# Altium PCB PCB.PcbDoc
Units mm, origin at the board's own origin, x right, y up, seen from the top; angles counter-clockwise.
Board outline 65 x 50 mm, 2 copper layers (Top Layer, Bottom Layer); 104 components, 73 nets, 355 pads, 371 vias.
Unrouted connection lines stored in the file: 2.
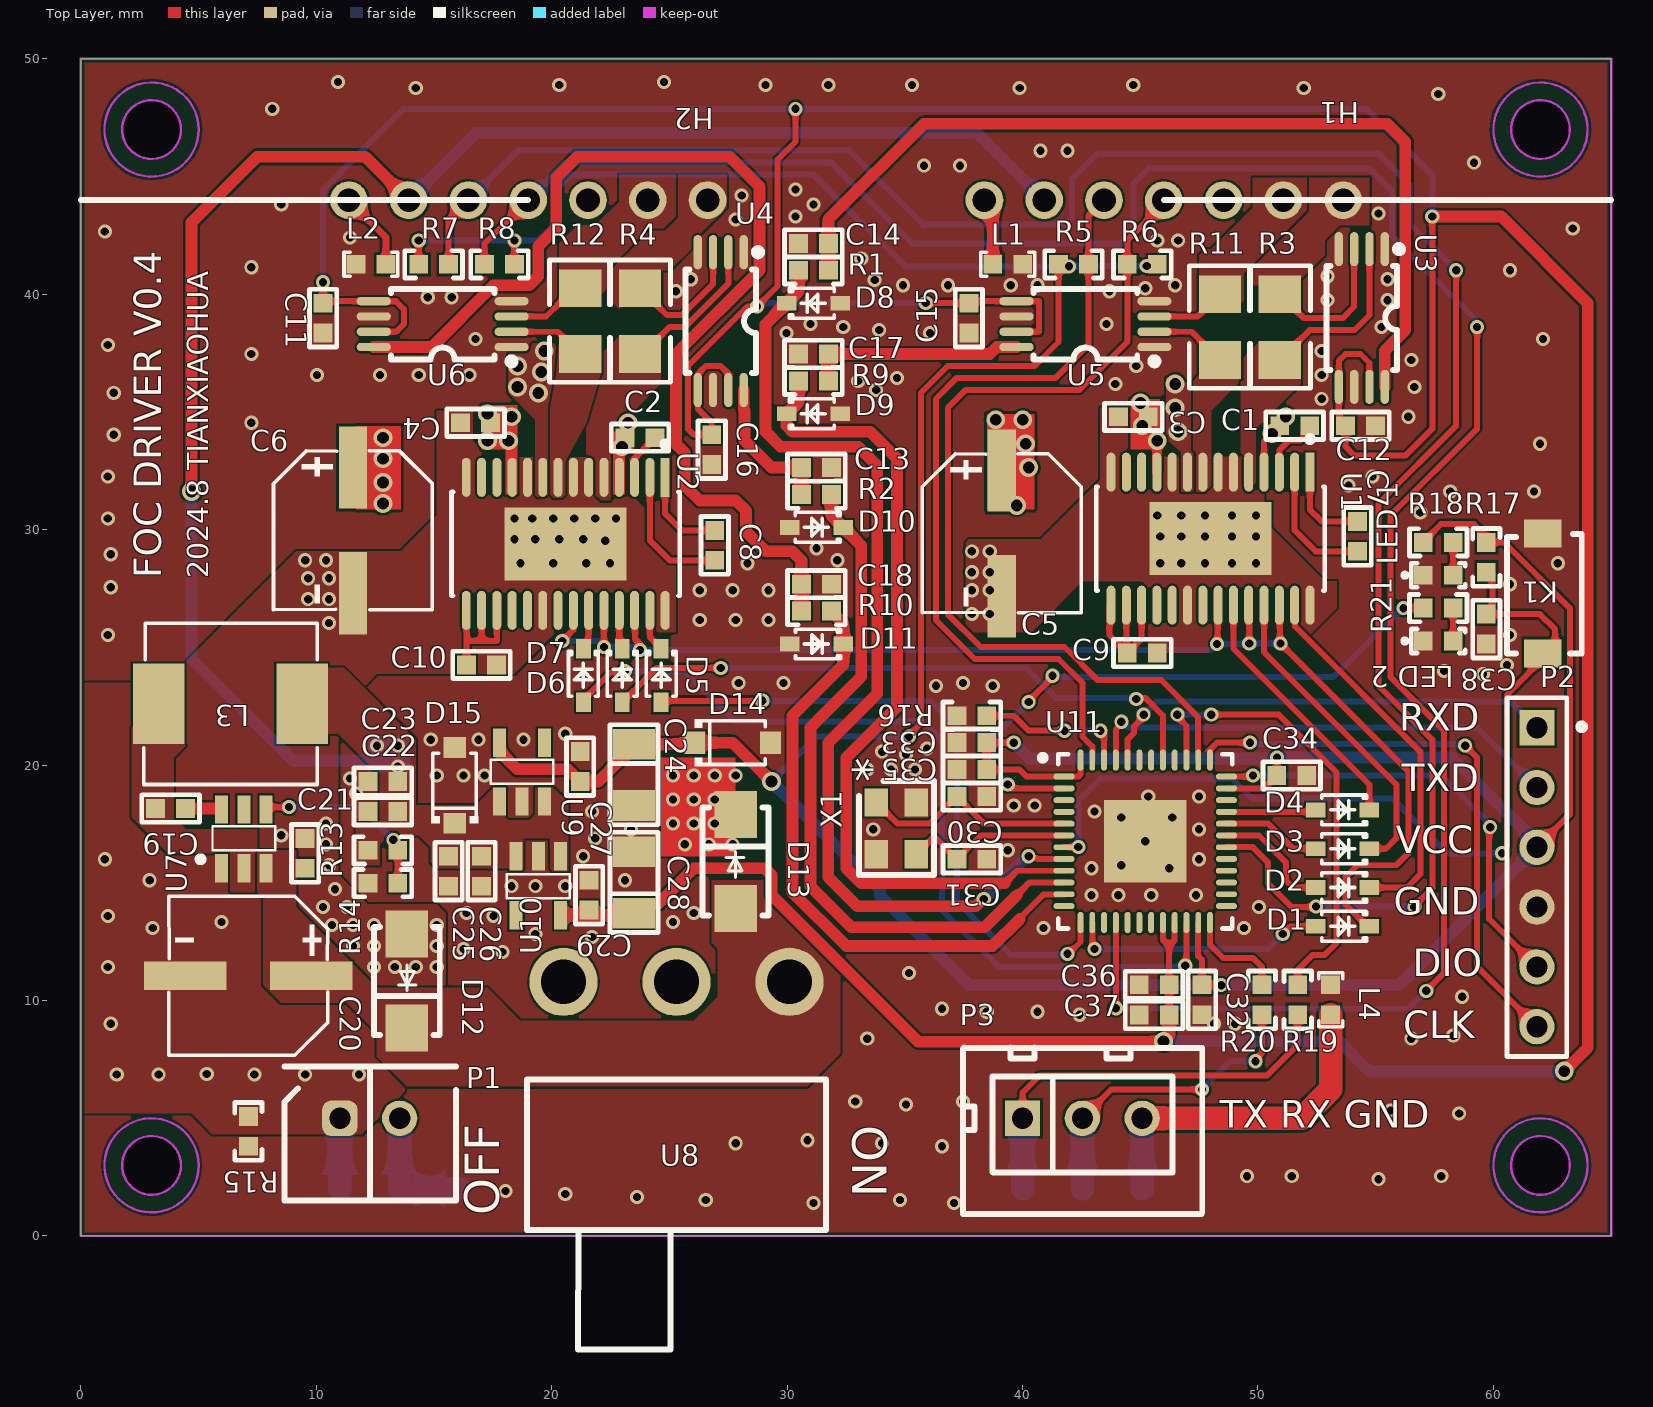
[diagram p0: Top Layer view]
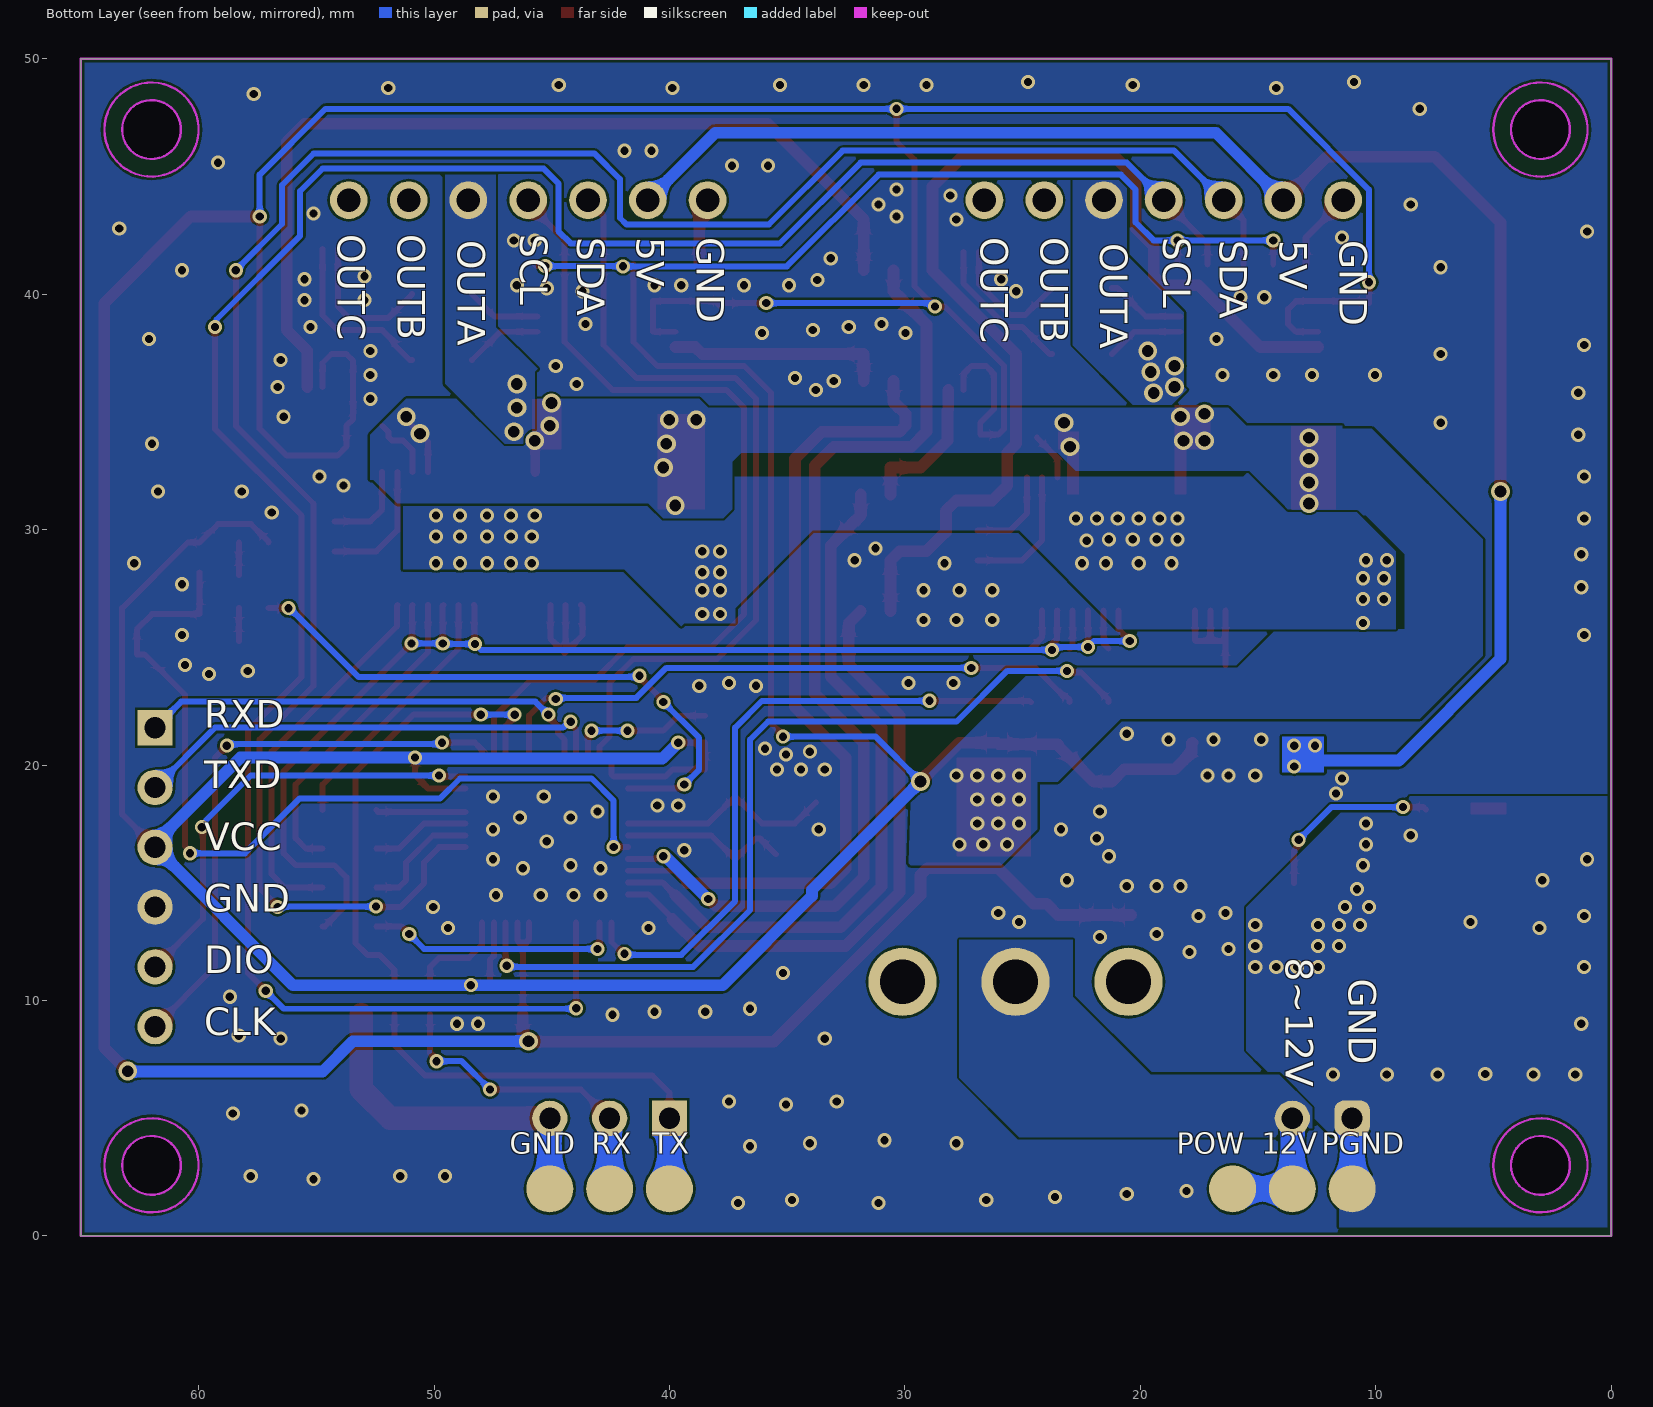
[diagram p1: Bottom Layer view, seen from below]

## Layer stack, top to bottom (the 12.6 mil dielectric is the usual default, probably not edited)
Top Solder: solder mask 0.0102, Solder Resist, Dk 3.5
Top Layer: signal copper 0.0356
Dielectric 1: dielectric 0.32, FR-4, Dk 4.8
Bottom Layer: signal copper 0.0356
Bottom Solder: solder mask 0.0102, Solder Resist, Dk 3.5

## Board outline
0,0 0,50 65,50 65,0
cut-out: 60.75,47 ccw(c62,47) 62,45.75 ccw(c62,47) 63.25,47 ccw(c62,47) 62,48.25 ccw(c62,47)
cut-out: 60.75,3 ccw(c62,3) 62,1.75 ccw(c62,3) 63.25,3 ccw(c62,3) 62,4.25 ccw(c62,3)
cut-out: 60.75,3 ccw(c62,3) 62,1.75 ccw(c62,3) 63.25,3 ccw(c62,3) 62,4.25 ccw(c62,3)
cut-out: 60.75,3 ccw(c62,3) 62,1.75 ccw(c62,3) 63.25,3 ccw(c62,3) 62,4.25 ccw(c62,3)
cut-out: 1.75,3 ccw(c3,3) 3,1.75 ccw(c3,3) 4.25,3 ccw(c3,3) 3,4.25 ccw(c3,3)
cut-out: 1.75,47 ccw(c3,47) 3,45.75 ccw(c3,47) 4.25,47 ccw(c3,47) 3,48.25 ccw(c3,47)

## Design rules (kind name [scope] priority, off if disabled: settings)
Clearance [All] p1: gap=0.1 ignorepadtopadclearanceinfootprint=FALSE except(0: Arc-Hole Track-Hole SMDPad-Hole THPad-Hole Via-Hole Fill-Hole Poly-Hole Region-Hole Text-Hole; 0.102: Arc-Arc Arc-Track Arc-SMDPad Arc-THPad Track-Track Track-SMDPad Track-THPad SMDPad-SMDPad SMDPad-THPad THPad-THPad; 0.127: Arc-Via Track-Via SMDPad-Via SMDPad-Text THPad-Via Via-Via; 0.254: Arc-Text Track-Text THPad-Text Via-Text Fill-Text Poly-Text Region-Text Text-Text)
HoleSize [All] p1: absolutevalues=TRUE maxlimit=30 minlimit=0.025 maxpercent=80.000 minpercent=20.000
HoleToHoleClearance [All] p1: gap=0.152 allowstackedmicrovias=TRUE
MinimumSolderMaskSliver [All] p1: minsoldermaskwidth=0
PlaneClearance [All] p1: clearance=0.254
PlaneConnect [All] p1: planeconnectstyle=Direct reliefexpansion=0.508 reliefentries=4 reliefconductorwidth=0.254 reliefairgap=0.254
PolygonConnect [All] p1: connectstyle=Direct reliefconductorwidth=0.254 reliefentries=4 polygonreliefangle="90 Angle" airgapwidth=0.254
RoutingVias [All] p1: holewidth=0.711 width=1.27 viastyle="Through Hole" minholewidth=0.3 minwidth=0.5 maxholewidth=30 maxwidth=30
SilkToSilkClearance [All] p1: silktosilkclearance=0
SilkToSolderMaskClearance [IsPad] p1: minsilkscreentomaskgap=0 clearancetoexposedcopper=TRUE
SolderMaskExpansion [All] p1: expansion=0.102 istentingtop=FALSE
Width [All] p1: maxlimit=3 minlimit=0.1 preferedwidth=0.254
23 further rules are at their usual default settings.

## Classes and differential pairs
component class Sheet0-MCU: C30 C31 C32 C33 C34 C35 C36 C37 C38 GND K1 L4 "LED 1" "LED 2" P2 P3 R16 R17 R18 R19 R20 R21 RX TX U11 X1
component class Sheet2-power: 12V C19 C20 C21 C22 C23 C24 C25 C26 C27 C28 C29 D12 D13 D14 D15 L3 P1 PGND POW R13 R14 R15 U7 U8 U9 U10
component class Sheet1-driver: C1 C2 C3 C4 C5 C6 C7 C8 C9 C10 C11 C12 C13 C14 C15 C16 C17 C18 D1 D2 D3 D4 D5 D6 D7 D8 D9 D10 D11 H1 H2 L1 L2 R1 R2 R3 R4 R5 R6 R7 R8 R9 R10 R11 R12 U1 U2 U3 U4 U5 U6

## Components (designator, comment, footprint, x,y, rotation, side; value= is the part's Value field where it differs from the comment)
12V "test" test#1 13.716,1.905 r180 bottom
C1 "100nF" CC1608-0603 51.562,34.417 r180 top
C2 "100nF" CC1608-0603 23.749,33.909 r180 top
C3 "100NF 50V" CC1608-0603 44.704,34.798 r180 top
C4 "100NF 50V" CC1608-0603 16.764,34.544 r180 top
C5 "35V 100uF" CAP-SMD_D6.3 39.116,29.845 r270 top
C6 "35V 100uF" CAP-SMD_D6.3 11.557,29.972 r270 top locked
C7 "0.01uF" CC1608-0603 54.229,29.718 r90 top
C8 "0.01uF" CC1608-0603 26.924,29.337 r90 top
C9 "0.47UF" CC1608-0603 45.085,24.765 r0 top
C10 "0.47UF" CC1608-0603 17.018,24.257 r0 top
C11 "100nF" CC1608-0603 10.287,38.989 r270 top
C12 "100nF" CC1608-0603 54.356,34.417 r0 top
C13 "2.2nF" CC1608-0603 31.242,32.639 r180 top
C14 "2.2nF" CC1608-0603 31.115,42.164 r0 top
C15 "100nF" CC1608-0603 37.719,38.989 r270 top
C16 "100nF" CC1608-0603 26.797,33.401 r270 top
C17 "2.2nF" CC1608-0603 31.115,37.465 r0 top
C18 "2.2nF" CC1608-0603 31.242,27.686 r180 top
C19 "100nF" CC1608-0603 3.81,18.161 r180 top
C20 "35V 100uF" CAP-SMD_D6.3 7.109,11.049 r180 top
C21 "100NF 50V" CC1608-0603 9.525,16.256 r270 top
C22 "22uf" CC1608-0603 12.827,18.034 r0 top
C23 "22uf" CC1608-0603 12.827,19.304 r0 top
C24 "22uF" TAN-A-1206 23.495,19.621 r270 top
C25 "2.2uf" CC1608-0603 15.621,15.494 r90 top
C26 "100nF" CC1608-0603 17.018,15.494 r90 top
C27 "100NF" CC1608-0603 21.209,19.939 r90 top
C28 "22uF" TAN-A-1206 23.495,14.986 r90 top
C29 "100NF" CC1608-0603 21.59,14.478 r90 top
C30 "20pF" CC1608-0603 37.846,18.669 r180 top
C31 "20pF" CC1608-0603 37.846,16.002 r180 top
C32 "100NF" CC1608-0603 47.625,10.033 r90 top
C33 "100NF" CC1608-0603 37.846,20.955 r0 top
C34 "100NF" CC1608-0603 51.435,19.558 r180 top
C35 "100NF" CC1608-0603 37.846,19.812 r0 top
C36 "100NF" CC1608-0603 45.593,10.668 r0 top
C37 "1uF" CC1608-0603 45.593,9.388 r0 top
C38 "1UF" CC1608-0603 59.7,25.781 r90 top
D1 "1N4148" SOD-323 53.594,13.155 r180 top
D2 "1N4148" SOD-323 53.594,14.802 r180 top
D3 "1N4148" SOD-323 53.594,16.45 r180 top
D4 "1N4148" SOD-323 53.594,18.098 r180 top
D5 "1N4148" SOD-323 24.648,23.812 r270 top
D6 "1N4148" SOD-323 22.997,23.812 r270 top
D7 "1N4148" SOD-323 21.346,23.812 r270 top
D8 "PESD3V3L1BA" SOD-323 31.115,39.624 r0 top
D9 "PESD3V3L1BA" SOD-323 31.115,34.925 r0 top
D10 "PESD3V3L1BA" SOD-323 31.242,30.099 r180 top
D11 "PESD3V3L1BA" SOD-323 31.245,25.146 r180 top
D12 "SMBJ24A" "DO-214 AA" 13.843,10.827 r90 top
D13 "SS34" "DO-214 AA" 27.813,15.907 r270 top
D14 "SMFJ5.0A" SOD-123 27.686,20.955 r0 top
D15 "SMFJ5.0A" SOD-123 15.875,19.136 r90 top
GND "test" test#2 45.339,1.778 r180 bottom
H1 "Header_7P_Curved" HEADER_2_54_7PW 53.62,44 r180 top locked
H2 "Header_7P_Curved" HEADER_2_54_7PW 26.62,44 r180 top locked
K1 "KEY 3*4" "KEY 3*4" 62.103,24.745 r90 top
L1 "68nH 200mA" Inductor-0603 39.37,41.275 r0 top
L2 "68nH 200mA" Inductor-0603 12.319,41.275 r180 top
L3 "15uH" Inductor-0630 6.35,22.606 r180 top locked
L4 "68nH 200mA" Inductor-0603 53.086,10.033 r90 top
"LED 1" "LED 0603" "LED 0603" 57.658,28.067 r180 top
"LED 2" "LED 0603" "LED 0603" 57.658,25.273 r180 top
P1 "Header 2" HX2.54-2 11,5 r0 top
P2 "Header 6" HDR1X6 61.849,21.59 r270 top
P3 "Header 3" HX2.54-3 40,5 r0 top
PGND "test" test#3 9.779,2.032 r180 bottom
POW "test" test#4 16.08,2 r180 bottom
R1 "22R" CR1608-0603 31.115,41.021 r0 top
R2 "22R" CR1608-0603 31.242,31.496 r180 top
R3 "0.01R" CR3216-1206 50.927,38.608 r270 top
R4 "0.01R" CR3216-1206 23.749,38.862 r270 top
R5 "4.7k/NC" CR1608-0603 42.164,41.275 r180 top
R6 "4.7k/NC" CR1608-0603 45.085,41.275 r0 top
R7 "4.7k/NC" CR1608-0603 14.986,41.275 r180 top
R8 "4.7k/NC" CR1608-0603 17.78,41.275 r0 top
R9 "22R" CR1608-0603 31.115,36.322 r0 top
R10 "22R" CR1608-0603 31.242,26.543 r180 top
R11 "0.01R" CR3216-1206 48.387,38.608 r270 top
R12 "0.01R" CR3216-1206 21.209,38.862 r270 top
R13 "100K 1%" CR1608-0603 12.827,16.383 r180 top
R14 "13.3K 1%" CR1608-0603 12.827,14.986 r0 top
R15 "0R" CR1608-0603 7.112,4.445 r90 top
R16 "10KR" CR1608-0603 37.846,22.098 r0 top
R17 "10K" CR1608-0603 59.7,28.829 r90 top
R18 "2K" CR1608-0603 57.658,29.464 r180 top
R19 "22R" CR1608-0603 51.689,10.033 r270 top
R20 "22R" CR1608-0603 50.165,10.033 r270 top
R21 "2K" CR1608-0603 57.658,26.67 r180 top
RX "test" test#5 42.418,1.651 r180 bottom
TX "test" test#6 39.497,1.27 r180 bottom
U1 "DRV8313PWPR" HTSSOP-28 47.982,29.622 r270 top
U2 "DRV8313PWPR" HTSSOP-28 20.594,29.4 r270 top
U3 "INA240A1PWR" TSSOP-8 54.412,38.995 r180 top
U4 "INA240A1PWR" TSSOP-8 27.178,38.862 r180 top locked
U5 "INA240A1PWR" TSSOP-8 42.672,38.735 r90 top
U6 "INA240A1PWR" TSSOP-8 15.367,38.735 r90 top locked
U7 "TPS54202DDCR" SOT23-6 6.858,16.891 r0 top
U8 "HX SS12D10G4" SW-TH_3P-SS12D06 25.299,10.795 r0 top locked
U9 "SPX3819M5-L-3.3/TR" SOT23-5 19.69,18.455 r180 top
U10 "SPX3819M5-L-3.3/TR" SOT23-5 18.476,16.129 r0 top
U11 "STM32G431CBU6" UFQFPN48_N 45.212,16.764 r0 top
X1 "3225_24M" XTAL-3225 35.482,18.415 r270 top

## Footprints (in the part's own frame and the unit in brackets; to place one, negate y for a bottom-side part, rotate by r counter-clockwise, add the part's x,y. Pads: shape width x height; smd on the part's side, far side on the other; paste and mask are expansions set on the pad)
CAP-SMD_D6.3 [mm] "直径6.3mm固态电容"
  rect 3.5x1.2 smd paste+0 mask+0.051: 1(-2.67,0) 2(2.67,0)
  silkscreen extent -3.38,-3.38 3.38,3.38, body extent -3.65,-3.3 3.65,3.3, height 5.9
CC1608-0603 [mm]
  rect 0.8x0.8 smd: 1(-0.635,0) 2(0.635,0)
  silkscreen extent -1.23,-0.58 1.23,0.58, body extent -0.8,-0.4 0.8,0.4, height 0.3
CR1608-0603 [mm]
  rect 0.8x0.8 smd: 1(-0.635,0) 2(0.635,0)
  silkscreen extent -1.23,-0.58 1.23,0.58, body extent -0.8,-0.4 0.8,0.4, height 0.45
CR3216-1206 [mm]
  rect 1.6x1.8 smd: 1(-1.4,0) 2(1.4,0)
  silkscreen extent -2.6,-1.3 2.6,1.3, body extent -1.6,-0.8 1.6,0.8, height 0.6
"DO-214 AA" [mm] "SMB"
  rect 2x1.8 smd: 1(-2,0) 2(2,0)
  silkscreen extent -2.3,-1.4 2.3,1.4, body extent -2.83,-1.8 2.57,1.8, height 2.4
HDR1X6 [mm] "Connector; Header; 6 Position"
  rect 1.5x1.5 hole 0.9: 1(0,0)
  round 1.5 hole 0.9: 2(2.54,0) 3(5.08,0) 4(7.62,0) 5(10.16,0) 6(12.7,0)
  silkscreen extent -1.27,-1.27 13.97,2.04, body extent -1.27,-1.27 13.97,1.27, height 8.54
HEADER_2_54_7PW [mm] "6P弯针"
  round 1.6 hole 1: 1(0,0) 2(2.54,0) 3(5.08,0) 4(7.62,0) 5(10.16,0) 6(12.7,0) 7(15.24,0)
  body extent -2.54,-7.48 17.78,0.37, height 5.8
HTSSOP-28 [mm]
  rect 1.655x0.381 smd paste+0 mask+0: 1(-2.825,4.225)
  rrect100% 1.655x0.381 smd paste+0 mask+0: 2(-2.825,3.575) 3(-2.825,2.925) 4(-2.825,2.275) 5(-2.825,1.625) 6(-2.825,0.975) 7(-2.825,0.325) 8(-2.825,-0.325) 9(-2.825,-0.975) 10(-2.825,-1.625) 11(-2.825,-2.275) 12(-2.825,-2.925) 13(-2.825,-3.575) 14(-2.825,-4.225) 15(2.825,-4.225) 16(2.825,-3.575) 17(2.825,-2.925) 18(2.825,-2.275) 19(2.825,-1.625) 20(2.825,-0.975) 21(2.825,-0.325) 22(2.825,0.325) 23(2.825,0.975) 24(2.825,1.625) 25(2.825,2.275) 26(2.825,2.925) 27(2.825,3.575) 28(2.825,4.225)
  rect 3.1x5.18 smd paste-1000 mask+0: 29(0,0)
  silkscreen extent -4.35,-4.85 2.2,4.85, body extent -3.9,-5.1 3.9,5.1, height 0.25
HX2.54-2 [mm] "两针白色插座（已加焊）"
  rrect50% 1.5x1.5 hole 0.9: 1(0,0)
  round 1.5 hole 0.9: 2(2.54,0)
  silkscreen extent -2.36,-3.5 4.94,2.2, body extent -2.48,-3.55 5.02,2.45, height 7
HX2.54-3 [mm]
  rect 1.5x1.5 hole 0.9: 1(0,0)
  round 1.5 hole 0.9: 2(2.54,0) 3(5.08,0)
  silkscreen extent -2.54,-4.06 7.63,3, body extent -2.41,-3.58 7.59,2.42, height 7
Inductor-0603 [mm]
  rect 0.8x0.8 smd: 1(-0.635,0) 2(0.635,0)
  silkscreen extent -1.14,-0.51 1.14,0.51, body extent -0.8,-0.43 0.8,0.43, height 0.48
Inductor-0630 [mm]
  rect 2.194x3.42 smd paste+0 mask+0.051: 1(3.048,0) 2(-3.048,0)
  silkscreen extent -3.68,-3.43 3.68,3.43, body extent -3.5,-3.3 3.5,3.3, height 2.8
"KEY 3*4" [mm]
  rect 1.2x1.6 smd: 1(0,0) 2(5.1,0)
  silkscreen extent 0,-1.65 5.08,1.52, body extent 0.25,-1.71 4.7,1.46, height 2.01
"LED 0603" [mm]
  rect 0.8x0.8 smd: 1(-0.635,0) 2(0.635,0)
  silkscreen extent -1.14,-0.51 1.48,0.51, body extent -0.8,-0.4 0.8,0.4, height 0.6
SOD-123 [mm]
  rect 0.88x0.96 smd: 1(-1.61,0) 2(1.61,0)
  silkscreen extent -1.6,-1 1.38,1, body extent -1.9,-0.8 1.8,0.8, height 1.32
SOD-323 [mm]
  rect 0.83x0.63 smd paste+0 mask+0.05: 1(-1.14,0) 2(1.14,0)
  silkscreen extent -1.02,-0.64 0.89,0.64, body extent -1.27,-0.68 1.33,0.68, height 1.1
SOT23-5 [mm] "适用于MIC5205"
  rect 0.55x1.2 smd: 1(1.905,0) 2(0.955,0) 3(0.005,0) 4(0.005,-2.5) 5(1.905,-2.5)
  silkscreen extent -0.38,-1.78 2.29,-0.76, body extent -0.6,-2.82 2.5,0.38, height 1.45
SOT23-6 [mm]
  rect 0.55x1.2 smd: 1(-0.889,-1.27) 2(0.061,-1.27) 3(1.011,-1.27) 4(1.011,1.23) 5(0.061,1.23) 6(-0.889,1.23)
  silkscreen extent -1.9,-1.02 1.4,0.51, body extent -1.39,-1.4 1.51,1.4, height 1.45
SW-TH_3P-SS12D06 [mm]
  round 2.9 hole 1.9 paste+0 mask+0.051: 1(-4.8,0) 2(0,0) 3(4.8,0)
  silkscreen extent -6.35,-15.62 6.35,-4.15, body extent -6.35,-15.68 6.35,-4.19, height 6.7
TAN-A-1206 [mm]
  rect 1.3x1.8 smd: 1(-1.27,0) 2(1.333,0)
  silkscreen extent -2.1,-1.02 2.16,1.02, body extent -1.66,-0.8 1.54,0.8, height 1.6
test#1 [mm]
  round 2 smd: 0(0.176,0.095)
test#2 [mm]
  round 2 smd: 0(0.259,0.222)
test#3 [mm]
  round 2 smd: 0(-1.221,-0.032)
test#4 [mm]
  round 2 smd: 0(0,0)
test#5 [mm]
  round 2 smd: 0(-0.122,0.349)
test#6 [mm]
  round 2 smd: 0(-0.503,0.73)
TSSOP-8 [mm]
  oval 0.353x1.454 smd: 1(-0.975,-2.927) 2(-0.325,-2.927) 3(0.325,-2.927) 4(0.975,-2.927) 5(0.975,2.927) 6(0.325,2.927) 7(-0.325,2.927) 8(-0.975,2.927)
  silkscreen extent -1.73,-3.08 1.5,2.2, body extent -1.43,-3.17 1.57,3.11, height 1.09
UFQFPN48_N [mm] "QFN, 48-Leads, Body 7.1x7.1mm, Pitch 0.5mm, Thermal Pad 5.6x5.6mm, IPC Medium Density"
  oval 0.9x0.25 smd: 1(-3.45,2.75) 2(-3.45,2.25) 3(-3.45,1.75) 4(-3.45,1.25) 5(-3.45,0.75) 6(-3.45,0.25) 7(-3.45,-0.25) 8(-3.45,-0.75) 9(-3.45,-1.25) 10(-3.45,-1.75) 11(-3.45,-2.25) 12(-3.45,-2.75) 25(3.45,-2.75) 26(3.45,-2.25) 27(3.45,-1.75) 28(3.45,-1.25) 29(3.45,-0.75) 30(3.45,-0.25) 31(3.45,0.25) 32(3.45,0.75) 33(3.45,1.25) 34(3.45,1.75) 35(3.45,2.25) 36(3.45,2.75)
  oval 0.25x0.9 smd: 13(-2.75,-3.45) 14(-2.25,-3.45) 15(-1.75,-3.45) 16(-1.25,-3.45) 17(-0.75,-3.45) 18(-0.25,-3.45) 19(0.25,-3.45) 20(0.75,-3.45) 21(1.25,-3.45) 22(1.75,-3.45) 23(2.25,-3.45) 24(2.75,-3.45) 37(2.75,3.45) 38(2.25,3.45) 39(1.75,3.45) 40(1.25,3.45) 41(0.75,3.45) 42(0.25,3.45) 43(-0.25,3.45) 44(-0.75,3.45) 45(-1.25,3.45) 46(-1.75,3.45) 47(-2.25,3.45) 48(-2.75,3.45)
  rect 3.5x3.5 smd: 49(0,0)
  silkscreen extent -4.47,-3.7 3.7,3.7, body extent -3.5,-3.5 3.5,3.5, height 0.55
XTAL-3225 [mm]
  rect 1.2x1 smd: 1(0,-1.7) 2(2.2,-1.7) 3(2.2,0) 4(0,0)
  silkscreen extent -0.91,-2.44 3.07,0.76, body extent -0.43,-2.15 2.77,0.35, height 0.61

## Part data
12V GND PGND POW RX TX: "测试点"
C1 C2 C3 C4 C7 C8 C9 C10 C11 C12 C13 C14 C15 C16 C17 C18 C19 C21 C22 C23 C25 C26 C30 C31 C32 C33 C34 C35 C36 C37 C38: library part "Cap Chip 0603", "0603封装的电容"
C5 C6 C20: library part "Cap ECAP SMD", "铝点解电容", BOM_Manufacturer=PANASONIC, BOM_Manufacturer Part=EEEFP1C681AP
C24 C28: library part "CAP TAN-A-1206", "钽电容"
C27 C29: library part "Chip capacitor", "贴片电容"
D1 D2 D3 D4 D5 D6 D7: "1N5819 SOD-323封装 小体积SS14 印S4 肖特基二极管"
D8 D9 D10 D11: "SOD-323 3.3V 双向ESD防静电二极管保护芯片", JLCPCB Part Class="Extended Part", Manufacturer=MDD, Manufacturer Part=SMAJ6.5CA
D12: library part SMBJ18A, "TVS稳压二极管"
D13: "肖特基二极管"
D14 D15: "5V单向贴片TVS瞬变抑制二极管"
H1 H2: "弯的6P排针"
K1: "轻触开关按键"
L1 L2 L4: library part Inductor-0603, "贴片电感 0603封装"
L3: library part Inductor-0630, "贴片电感 0630封装"
P1: "Header, 2-Pin"
P2: "Header, 6-Pin"
P3: "Header, 3-Pin"
R1 R2 R5 R6 R7 R8 R9 R10 R13 R14 R15 R16 R17 R18 R19 R20 R21: library part "Resistor Chip 0603", "0603封装电阻"
R3 R4 R11 R12: library part "Resistor Chip 1206", "1206封装电阻"
U1 U2: library part DRV8313, "独立控制的半 H 桥驱动器,主要用于驱动一个三项无刷电机IC MOTOR DRIVER 8V-60V 28HTSSOP", Case/Package=HTSSOP, Max Operating Temperature=125°C, Max Supply Voltage=60V, Min Operating Temperature=-40°C, Min Supply Voltage=8V, Output Current=1.75A, Package Quantity=2000
U3 U4 U5 U6: "超精密电流检测放大器"
U7: "同步降压转换器芯片 500Khz 4.2~28V输入，2A输出"
U8: library part SW-TH_3P-SS12D06, BOM_JLCPCB Part Class="Extended Part", BOM_Manufacturer=hanxia(韩下)
U9 U10: "LDO 3.3V , SOT-23-5 500ma"
U11: JLCPCB Part Class="Extended Part", Manufacturer=ST(意法半导体)
X1: library part "XTAL 3225", "3225封装的晶振"

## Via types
v1: diameter 0.6, hole 0.35, Top Layer to Bottom Layer, 324 vias
v2: diameter 0.8, hole 0.5, Top Layer to Bottom Layer, 32 vias
v3: diameter 0.6, hole 0.35, Top Layer to Bottom Layer, tented both sides, 15 vias

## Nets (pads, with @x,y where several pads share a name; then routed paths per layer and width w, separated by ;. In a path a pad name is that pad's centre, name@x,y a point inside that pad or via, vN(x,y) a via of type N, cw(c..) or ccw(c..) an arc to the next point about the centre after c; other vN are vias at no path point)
3.3V: C24.1 C27.1 C32.2 C33.2 C34.2 C35.2 D14.1 P2.3 R5.2 R6.2 R7.2 R8.2 R17.2 R18.2 U9.5 U11.1 U11.23 U11.35 U11.48 | length 178.1
  Top Layer w0.254: R7.2 v1(14.351,42.291) ; R8.2 v1(18.415,42.291) ; v1(35.179,21.209) 35.179,21.277 35.687,21.785 35.687,35.814 36.83,36.957 40.513,36.957 41.529,37.973 R5.2 41.616,41.188 v1(41.972,41.188) ; v1(39.624,20.955) C33.2 C35.2 39.878,19.812 40.176,19.514 U11.1 42.374,19.514 42.462,19.602 U11.48 ; v1(45.277,41.204) 45.649,41.204 R6.2 ; U11.23 47.462,11.902 47.625,11.739 C32.2 48.421,10.668 v1(48.436,10.653) ; U11.35 48.672,19.004 50.246,19.004 C34.2 v1@50.8,20.32 ; R18.2 57.023,29.482 57.785,30.244 59.174,30.244 59.681,29.737 59.954,29.464 60.452,29.464 63.246,26.67 63.246,17.907 P2.3
  Top Layer w0.5: U9.5 17.81,20.93 17.81,20.548 18.536,19.822 20.691,19.822 C27.1 21.971,19.304 23.495,20.828 C24.1 26.012,20.892 D14.1 27.686,20.955 v2(29.337,19.304)
  Bottom Layer w0.254: v1(14.351,42.291) v1(18.415,42.291) 19.431,42.291 20.193,43.053 20.193,44.45 20.828,45.085 31.115,45.085 35.012,41.188 v1(41.972,41.188) ; v2(29.337,19.304) 31.242,21.209 v1(35.179,21.209) ; v1@42.092,41.188 42.1,41.196 45.269,41.196 v1(45.277,41.204)
  Bottom Layer w0.5: v2(29.337,19.304) 33.945,14.696 33.945,14.442 37.734,10.653 v1(48.436,10.653) 55.992,10.653 P2.3 61.849,16.705 58.231,20.323 v1(50.806,20.323) 50.761,20.278 40.301,20.278 v1(39.624,20.955)
5V: C22.2 C23.2 C25.2 C26.2 D15.1 H1.6 H2.6 L3.2 R13.2 U9.1 U9.3 U10.1 U10.3 | length 68.8
  Top Layer w0.5: v2(4.699,31.623) 4.699,43.053 7.493,45.847 12.073,45.847 H2.6
  Bottom Layer w0.5: v2(4.699,31.623) 4.699,24.511 9.017,20.193 12.7,20.193 ; H2.6 16.783,46.863 38.057,46.863 H1.6
  other v1: 13.462,19.939 12.573,20.828 13.462,20.828
ADC1_IN1: D8.1 R1.1 U11.8 | length 42.6
  Top Layer w0.254: v1(40.259,16.129) 40.325,16.063 40.591,16.063 40.64,16.014 U11.8
  Top Layer w0.5: R1.1 30.48,40.129 D8.1 29.083,38.732 29.083,34.163 29.718,33.528 33.02,33.528 33.83,32.718 33.83,23.035 31.75,20.955 31.75,15.24 32.987,14.003 38.021,14.003 38.327,14.309 v1(38.354,14.309)
  Bottom Layer w0.5: v1(38.354,14.309) 40.155,16.11 40.24,16.11 v1(40.259,16.129)
ADC1_IN2: D9.1 R9.1 U11.9 | length 35.4
  Top Layer w0.254: 39.243,14.986 39.771,15.514 U11.9
  Top Layer w0.5: R9.1 30.48,35.43 D9.1 29.975,34.414 30.226,34.163 33.528,34.163 34.671,33.02 34.671,22.479 32.512,20.32 32.512,15.621 33.147,14.986 39.243,14.986
ADC1_IN3: D10.1 R2.1 U11.10 | length 30.3
  Top Layer w0.254: 39.751,14.478 40.287,15.014 U11.10
  Top Layer w0.5: R2.1 31.877,30.604 D10.1 33.152,29.329 33.152,23.754 30.988,21.59 30.988,14.859 32.733,13.114 38.387,13.114 39.751,14.478
ADC1_IN4: D11.1 R10.1 U11.11 | length 26.5
  Top Layer w0.254: 39.878,13.462 39.878,13.498 40.894,14.514 U11.11
  Top Layer w0.5: R10.1 32.385,26.035 D11.1 32.385,24.257 30.226,22.098 30.226,14.605 32.512,12.319 38.735,12.319 39.878,13.462
AGND: "LED 1.2" "LED 2.2" C11.2 C12.2 C13.1 C14.1 C15.2 C16.2 C17.1 C18.1 C22.1 C23.1 C24.2 C25.1 C26.1 C27.2 C28.2 C29.2 C30.1 C31.1 C32.1 C33.1 C34.1 C35.1 C36.1 C37.1 C38.1 D8.2 D9.2 D10.2 D11.2 D14.2 D15.2 K1.2 L1.2 L2.2 L4.2 P2.4 R14.1 R15.1 R16.1 U3.1 U3.4 U3.6 U4.1 U4.4 U4.6 U5.1 U5.4 U5.6 U6.1 U6.4 U6.6 U9.2 U10.2 U11.49 X1.2 X1.4
  other v1: 31.115,1.397 37.084,1.397 26.543,1.524 34.798,1.524 23.622,1.651 20.574,1.778 18.034,1.905 55.118,2.413 49.53,2.54 51.435,2.54 57.785,2.54 36.576,3.81 27.813,3.937 34.036,3.937 30.861,4.064 58.547,5.207 55.626,5.334 35.052,5.588 32.893,5.715 37.465,5.715 33.401,8.382 56.515,8.382 58.293,8.509 48.133,9.017 49.022,9.017 42.418,9.398 38.481,9.525 40.64,9.525 36.576,9.652 58.674,10.16 35.179,11.176 17.907,12.065 16.256,12.192 21.717,12.7 19.304,12.827 40.894,13.081 49.403,13.081 25.146,13.335 17.526,13.589 16.383,13.716 26.035,13.716 50.038,13.97 42.926,14.478 44.069,14.478 45.466,14.478 47.371,14.478 18.288,14.859 19.304,14.859 20.574,14.859 23.114,15.113 42.926,15.621 46.228,15.621 44.196,15.748 47.498,16.002 21.336,16.129 39.37,16.383 45.212,16.764 21.844,16.891 23.368,17.272 33.655,17.272 47.498,17.272 44.196,17.78 46.355,17.78 21.717,18.034 43.053,18.034 39.624,18.288 40.513,18.288 45.339,18.669 47.498,18.669 11.684,18.796 11.43,19.431 15.113,19.558 16.256,19.558 17.145,19.558 33.401,19.812 34.417,19.812 35.433,19.812 35.052,20.447 34.036,20.574 35.941,20.701 14.859,21.082 16.891,21.082 18.796,21.082 20.574,21.336 36.322,23.368 38.735,23.368 27.94,23.495 29.845,23.495 37.465,23.495 59.563,23.876 57.912,24.003 60.579,24.257 1.143,25.527 60.706,25.527 26.289,26.162 27.813,26.162 29.21,26.162 26.289,27.432 27.686,27.432 29.21,27.432 1.27,27.559 60.706,27.686 28.321,28.575 62.738,28.575 32.131,28.702 1.27,28.956 31.242,29.21 1.143,30.48 56.896,30.734 58.166,31.623 61.722,31.623 53.848,31.877 1.143,32.258 54.864,32.258 61.976,33.655 1.397,34.036 7.239,34.544 56.388,34.798 52.705,35.56 1.397,35.814 33.782,35.941 56.642,36.068 43.942,36.195 33.02,36.322 34.671,36.449 10.033,36.576 12.7,36.576 14.351,36.576 16.51,36.576 52.705,36.576 44.831,36.957 56.515,37.211 7.239,37.465 52.705,37.592 1.143,37.846 16.764,38.1 62.103,38.1 29.972,38.354 36.068,38.354 33.909,38.481 32.385,38.608 55.245,38.608 30.988,38.735 43.561,38.735 52.959,39.751 55.499,39.751 14.732,39.878 15.748,39.878 25.273,40.132 43.688,40.132 45.212,40.259 34.925,40.386 36.83,40.386 39.497,40.386 40.64,40.386 46.482,40.386 33.717,40.613 25.908,40.64 55.499,40.64 52.959,40.767 60.706,41.021 7.239,41.148 33.147,41.529 45.72,42.291 46.609,42.291 11.43,42.418 1.016,42.672 63.373,42.799 27.813,43.18 30.353,43.307 55.118,43.434 8.509,43.815 31.115,43.815 28.067,44.196 30.353,44.45 35.814,45.466 37.338,45.466 59.182,45.593 40.767,46.101 41.91,46.101 8.128,47.879 57.658,48.514 14.224,48.768 39.878,48.768 51.943,48.768 20.32,48.895 29.083,48.895 31.75,48.895 35.306,48.895 44.704,48.895 10.922,49.022 24.765,49.022
BOOT0: R16.2 U11.46 | length 6.4
  Top Layer w0.254: R16.2 39.624,22.098 40.259,21.463 v1(41.783,21.463) ; v1(43.307,21.463) 43.307,21.369 43.462,21.214 U11.46
  Bottom Layer w0.254: v1(41.783,21.463) v1(43.307,21.463)
DRV_EN: D1.2 U11.14 | length 11
  Top Layer w0.254: U11.14 42.962,12.283 v1(43.053,12.192) ; v1(51.054,12.827) 51.381,13.154 D1.2
  Bottom Layer w0.254: v1(43.053,12.192) 50.419,12.192 v1(51.054,12.827)
HSE_I: C30.2 U11.5 X1.1 | length 9.3
  Top Layer w0.254: X1.1 34.671,17.526 36.068,17.526 C30.2 38.366,17.514 U11.5
HSE_O: C31.2 U11.6 X1.3 | length 7.3
  Top Layer w0.254: X1.3 36.158,16.891 36.322,16.891 C31.2 38.223,17.014 U11.6
I2C1_SCL: H1.4 R6.1 U11.38 | length 38.5
  Top Layer w0.254: H1.4 46,43.841 44.45,42.291 R6.1 44.45,37.973 42.418,35.941 37.592,35.941 36.83,35.179 36.83,26.416 38.227,25.019 41.783,25.019 43.18,23.622 45.879,23.622 47.462,22.039 U11.38
I2C1_SDA: H1.5 R5.1 U11.47 | length 34
  Top Layer w0.254: U11.47 42.962,20.792 42.545,21.209 42.545,23.495 41.529,24.511 37.973,24.511 36.322,26.162 36.322,35.56 37.211,36.449 41.402,36.449 42.799,37.846 R5.1 42.799,43.339 H1.5
I2C2_SCL: H2.4 R8.1 U11.16 | length 100.6
  Top Layer w0.254: R8.1 17.145,42.145 H2.4 ; v1(43.961,9.671) U11.16 ; v1(57.15,10.414) 57.912,11.176 57.912,21.463 55.626,23.749 55.626,30.607 59.309,34.29 v1(59.309,38.608)
  Bottom Layer w0.254: H2.4 19,44.019 20.574,45.593 31.877,45.593 35.306,42.164 44.196,42.164 44.717,42.685 44.717,44.717 45.339,45.339 54.737,45.339 55.689,44.386 55.689,42.481 59.243,38.928 59.243,38.674 v1(59.309,38.608) ; v1(43.961,9.671) 43.981,9.652 56.388,9.652 v1(57.15,10.414)
I2C2_SDA: H2.5 R7.1 U11.30 | length 91.7
  Top Layer w0.254: R7.1 15.621,43.161 H2.5 ; U11.30 49.78,16.514 50.419,15.875 50.419,14.986 51.435,13.97 v1@52.451,13.97 ; v1(56.642,13.97) 56.642,14.012 57.404,14.774 57.404,21.082 55.118,23.368 55.118,31.115 58.42,34.417 v1(58.42,41.021)
  Bottom Layer w0.254: H2.5 18.561,46.101 32.639,46.101 35.769,42.971 41.828,42.971 42.1,43.243 42.1,44.895 43.18,45.974 55.118,45.974 56.456,44.636 56.456,42.985 v1(58.42,41.021) ; v1(52.464,13.991) 56.621,13.991 v1(56.642,13.97)
LED0: R21.2 U11.2 | length 25.4
  Top Layer w0.254: v1(39.37,19.177) 39.533,19.014 U11.2 ; v1(40.259,22.682) 40.259,22.73 41.275,23.746 v1(41.275,23.795) ; v1(56.18,26.67) R21.2
  Bottom Layer w0.254: v1(39.37,19.177) 38.735,19.812 38.735,21.158 v1(40.259,22.682) ; v1(41.275,23.795) 41.321,23.749 53.213,23.749 56.134,26.67 v1(56.18,26.67)
M1_CS1: R3.2 U1.5 U3.2 | length 7.5
  Top Layer w0.254: R3.2 51.027,37.208 51.7,37.881 51.7,37.984 52.197,38.481 54.102,38.481 54.737,39.116 U3.2
M1_CS2: R11.2 U1.8 U5.2 | length 3.3
  Top Layer w0.254: U5.2 47.185,38.41 R11.2
M1_CS3: H1.3 U1.9
  other v2: 46.609,34.163 46.482,35.179 46.482,36.195
M1_IN1: D2.1 U1.27 | length 16
  Top Layer w0.254: U1.27 51.581,26.773 51.581,25.889 56.896,20.574 56.896,15.367 56.331,14.802 D2.1
M1_IN2: D3.1 U1.25 | length 13.6
  Top Layer w0.254: U1.25 50.257,24.8 55.88,19.177 55.88,16.891 55.439,16.45 D3.1
M1_IN3: D4.1 U1.23 | length 11.1
  Top Layer w0.254: U1.23 48.957,24.957 54.734,19.18 D4.1
M2_CS1: R4.2 U2.5 U4.2 | length 6.3
  Top Layer w0.254: R4.2 23.849,37.462 24.995,38.608 25.654,38.608 27.503,40.457 U4.2
M2_CS2: R12.2 U2.8 U6.2 | length 3.3
  Top Layer w0.254: U6.2 20.261,38.41 R12.2
M2_CS3: H2.3 U2.9
  other v2: 19.431,35.814 18.542,36.068 19.558,36.703 18.542,36.957 19.685,37.592
M2_IN1: D5.1 U2.27 | length 1.8
  Top Layer w0.254: U2.27 24.169,25.431 D5.1
M2_IN2: D6.1 U2.25 | length 1.7
  Top Layer w0.254: U2.25 22.869,25.08 D6.1
M2_IN3: D7.1 U2.23 | length 1.7
  Top Layer w0.254: D7.1 21.569,25.175 U2.23
M_EN: D1.1 U1.22 U1.24 U1.26 U2.22 U2.24 U2.26 | length 57.2
  Top Layer w0.254: v1(20.447,25.273) 20.919,25.745 U2.22 ; v1@22.219,25.025 U2.24 ; U2.26 23.541,26.553 23.541,25.354 v1@23.749,25.146 ; v1(48.26,25.146) 48.284,25.17 48.284,26.773 U1.22 ; U1.24 49.631,26.773 v1(49.631,25.172) v1@49.657,25.146 ; U1.26 50.93,26.774 50.93,25.195 v1(50.953,25.172) 51.994,24.13 56.388,19.736 56.388,16.256 55.88,15.748 54.229,15.748 53.721,15.24 53.721,14.068 54.446,13.343 54.634,13.155 D1.1
  Bottom Layer w0.254: v1(20.447,25.273) 21.971,25.273 v1(22.225,25.019) 23.622,25.019 v1(23.749,24.892) 48.006,24.892 v1(48.26,25.146) 49.657,25.146 49.683,25.172 v1(50.953,25.172)
M_PWR: C1.2 C2.2 C3.1 C4.1 C5.1 C6.1 D13.1 U1.4 U1.11 U2.4 U2.11 | length 6.4
  Top Layer w0.254: C5.1@39.497,32.893 39.497,31.126 39.589,31.034 v2(39.751,31.034) ; v2(45.012,35.379) 45.066,35.325 45.066,35.071 C3.1 ; U1.4 50.257,33.747 C1.2
  Top Layer w0.4: U1.11 45.707,33.769 v2(45.72,33.782)
  other v1: 25.654,16.637 26.67,16.637 27.686,16.637 25.146,17.526 26.035,17.526 26.924,17.526 25.146,18.542 26.035,18.542 26.924,18.542 25.146,19.558 26.035,19.558 26.924,19.558 27.813,19.558
  other v2: 12.827,31.115 12.827,32.004 40.259,32.639 12.827,33.02 22.987,33.528 40.132,33.655 17.272,33.782 18.161,33.782 12.827,33.909 50.592,34.082 45.085,34.417 23.241,34.544 38.862,34.671 40.005,34.671 18.288,34.798 51.181,34.798 17.272,34.925
Net12V_0: 12V.0 P1.2 POW.0 U8.2 | length 5.5
  Bottom Layer w1: P1.2 12V.0 POW.0
NetC1_1: C1.1 U1.3 | length 2.8
  Top Layer w0.254: U1.3 50.907,33.381 51.308,33.782 51.775,33.782 51.924,33.931 51.924,34.144 C1.1
NetC2_1: C2.1 U2.3 | length 2
  Top Layer w0.254: U2.3 23.519,33.044 C2.1
NetC7_1: C7.1 U1.2 | length 5.5
  Top Layer w0.254: U1.2 51.557,29.977 52.451,29.083 C7.1
NetC7_2: C7.2 U1.1 | length 3.8
  Top Layer w0.254: U1.1 52.207,30.851 52.705,30.353 C7.2
NetC8_1: C8.1 U2.2 | length 5.8
  Top Layer w0.254: U2.2 24.169,29.552 25.019,28.702 C8.1
NetC8_2: C8.2 U2.1 | length 3.9
  Top Layer w0.254: U2.1 24.819,30.68 25.527,29.972 C8.2
NetC13_2: C13.2 R2.2 U4.8 | length 6.2
  Top Layer w0.5: U4.8 28.153,35.093 28.194,35.052 28.194,33.782 29.337,32.639 C13.2 R2.2
NetC14_2: C14.2 R1.2 U3.8 | length 39.4
  Top Layer w0.5: R1.2 C14.2 31.75,43.18 35.814,47.244 55.499,47.244 56.261,46.482 56.261,38.481 55.387,37.607 U3.8
NetC17_2: C17.2 R9.2 U5.8 | length 9.3
  Top Layer w0.5: R9.2 C17.2 38.608,37.465 38.903,37.76 U5.8
NetC18_2: C18.2 R10.2 U6.8 | length 45.6
  Top Layer w0.5: U6.8 14.9,37.76 17.526,40.386 19.05,40.386 19.431,40.767 19.431,42.037 20.193,42.799 20.193,44.958 21.082,45.847 27.559,45.847 28.829,44.577 28.829,41.021 25.273,37.465 25.273,33.655 25.654,33.274 25.654,31.877 26.289,31.242 27.813,31.242 28.258,30.797 28.258,29.909 29.083,29.083 30.226,29.083 30.607,28.702 C18.2 R10.2
NetC19_1: C19.1 U7.6
NetC19_2: C19.2 L3.1 U7.2
NetGND_0: GND.0 L4.1 P3.3 | length 14.7
  Top Layer w1: P3.3 51.863,5 53.086,6.223 L4.1
  Bottom Layer w1: GND.0 P3.3
NetH1_7: H1.7 L1.1 | length 2.9
  Top Layer w0.5: H1.7 38.735,43.645 L1.1
NetH2_7: H2.7 L2.1 | length 3.4
  Top Layer w0.3: H2.7 11.38,43.992 12.954,42.418 L2.1
"NetLED 1_1": "LED 1.1" R18.1 | length 1.4
  Top Layer w0.254: 58.293,28.067 R18.1
"NetLED 2_1": "LED 2.1" R21.1 | length 1.4
  Top Layer w0.254: 58.293,25.273 R21.1
NetP3_1: P3.1 R19.2 TX.0 | length 17.9
  Top Layer w0.254: P3.1 40,6.091 40.721,6.812 50.373,6.812 51.689,8.128 R19.2
  Bottom Layer w1: TX.0 P3.1
NetP3_2: P3.2 R20.2 RX.0 | length 13.4
  Top Layer w0.254: P3.2 43.763,6.223 v1(47.625,6.223) ; v1(49.9,7.424) 49.9,7.517 50.165,7.782 R20.2
  Bottom Layer w0.254: v1(47.625,6.223) 48.826,7.424 v1(49.9,7.424)
  Bottom Layer w1: RX.0 P3.2
NetR13_1: R13.1 R14.2 U7.4 | length 7.9
  Top Layer w0.254: U7.4 7.967,18.219 v1(8.834,18.219) ; v1(13.271,16.828) 13.271,16.573 R13.1 R14.2
  Bottom Layer w0.254: v1(8.834,18.219) 11.88,18.219 v1(13.271,16.828)
NRST: C38.2 K1.1 R17.1 U11.7 | length 37.6
  Top Layer w0.254: U11.7 U11.7 42.363,16.516 v1(42.37,16.523) ; R17.1@59.954,28.194 59.954,26.416 61.976,26.416 62.621,25.771 62.621,24.705 62.297,24.705 60.579,22.987 60.579,16.558 60.371,16.35 v1(60.371,16.256)
  Bottom Layer w0.254: v1(42.37,16.523) 42.37,18.494 43.307,19.431 48.895,19.431 49.738,18.588 55.707,18.588 58.039,16.256 v1(60.371,16.256)
OUT1: H1.1 R3.1 U3.3 | length 6.2
  Top Layer w0.254: R3.1 51.946,38.989 53.594,38.989 54.087,39.482 U3.3
OUT2: H1.2 R11.1 U5.3 | length 3.2
  Top Layer w0.254: U5.3 47.439,39.06 R11.1
OUT3: H2.1 R4.1 U4.3 | length 5.5
  Top Layer w0.254: R4.1 24.895,39.116 25.527,39.116 26.853,40.442 U4.3
OUT4: H2.2 R12.1 U6.3 | length 3.4
  Top Layer w0.254: U6.3 19.756,39.06 20.958,40.262 R12.1
PGND: C3.2 C4.2 C5.2 C6.2 C9.2 C10.2 C20.2 C21.1 D12.2 P1.1 PGND.0 R15.2 U1.6 U1.7 U1.10 U1.14 U1.20 U1.28 U1.29 U2.6 U2.7 U2.10 U2.14 U2.20 U2.28 U2.29 U7.1 | length 3
  Bottom Layer w1: PGND.0 P1.1
  other v1: 1.524,6.858 3.302,6.858 7.366,6.858 9.525,6.858 11.811,6.858 5.346,6.885 1.27,9.017 1.143,11.43 12.446,11.43 13.335,11.43 14.224,11.43 15.113,11.43 11.557,12.319 12.446,12.319 15.113,12.319 3.048,13.081 10.668,13.208 11.557,13.208 12.446,13.208 15.113,13.208 5.969,13.335 1.143,13.589 10.287,13.97 11.303,13.97 10.795,14.732 2.921,15.113 10.541,15.748 1.016,16.002 10.414,16.637 8.509,17.018 10.414,17.526 10.541,26.035 37.846,26.416 38.608,26.416 9.652,27.051 10.541,27.051 37.846,27.432 38.608,27.432 9.652,27.94 10.541,27.94 37.846,28.194 38.608,28.194 18.669,28.575 20.066,28.575 21.463,28.575 22.479,28.575 9.525,28.702 10.414,28.702 37.846,29.083 38.608,29.083 22.278,29.537 18.415,29.591 19.304,29.591 20.32,29.591 21.336,29.591 18.415,30.48 19.177,30.48 20.066,30.48 20.955,30.48 21.844,30.48 22.733,30.48
  other v3: 45.847,28.575 46.736,28.575 47.752,28.575 48.895,28.575 49.911,28.575 45.847,29.718 46.736,29.718 47.752,29.718 48.895,29.718 49.911,29.718 45.72,30.607 46.736,30.607 47.752,30.607 48.895,30.607 49.911,30.607
PWM1_CH2: D2.2 U11.31 | length 5.2
  Top Layer w0.254: U11.31 50.042,17.014 51.181,15.875 51.181,15.113 51.492,14.802 D2.2
PWM1_CH3: D3.2 U11.32 | length 4.2
  Top Layer w0.254: U11.32 50.431,17.514 51.495,16.45 D3.2
PWM1_CH4: D4.2 U11.33 | length 3.8
  Top Layer w0.254: U11.33 52.371,18.014 D4.2
PWM2_CH1: D5.2 U11.13 | length 27.7
  Top Layer w0.254: D5.2 24.709,22.733 v1(28.956,22.733) ; v1(41.91,11.984) 41.956,11.984 42.462,12.49 U11.13
  Bottom Layer w0.254: v1(28.956,22.733) 36.068,22.733 37.211,21.59 37.211,14.224 39.497,11.938 41.864,11.938 v1(41.91,11.984)
PWM2_CH2: D6.2 U11.41 | length 26.4
  Top Layer w0.254: D6.2 22.997,22.772 23.185,22.96 23.285,22.96 24.455,24.13 v1(27.178,24.13) ; v1(44.831,22.814) 44.877,22.86 45.212,22.86 45.962,22.11 U11.41
  Bottom Layer w0.254: v1(27.178,24.13) 40.132,24.13 41.402,22.86 44.785,22.86 v1(44.831,22.814)
PWM2_CH3: D7.2 U11.22 | length 37.5
  Top Layer w0.254: D7.2 21.346,22.772 22.511,23.937 23.048,23.937 v1(23.114,24.003) ; v1(46.912,11.479) 46.962,11.529 U11.22
  Bottom Layer w0.254: v1(23.114,24.003) 25.649,24.003 27.808,21.844 35.814,21.844 36.576,21.082 36.576,13.843 38.989,11.43 46.863,11.43 v1(46.912,11.479)
RXD1: P2.1 U11.44 | length 19.6
  Top Layer w0.254: U11.44 44.462,21.094 44.727,21.359 44.727,21.633 45.145,22.05 v1(45.145,22.144)
  Bottom Layer w0.254: v1(45.145,22.144) 45.699,22.698 60.741,22.698 P2.1
SWCLK: P2.6 U11.37 | length 24.7
  Top Layer w0.254: U11.37 47.962,20.657 48.26,20.955 v1(49.657,20.955) ; v1(58.801,20.828) 59.309,20.32 59.309,11.43 P2.6
  Bottom Layer w0.254: v1(49.657,20.955) 49.721,20.892 58.737,20.892 v1(58.801,20.828)
SWDIO: P2.5 U11.36 | length 19
  Top Layer w0.254: U11.36 48.664,19.516 49.742,19.516 v1(49.784,19.558) ; v1(59.863,17.365) 59.817,17.319 59.817,13.462 P2.5
  Bottom Layer w0.254: v1(49.784,19.558) 57.785,19.558 59.693,17.65 59.693,17.629 59.863,17.459 v1(59.863,17.365)
TXD1: P2.2 U11.45 | length 20.5
  Top Layer w0.254: U11.45 43.962,21.516 44.196,21.75 v1(44.196,21.844)
  Bottom Layer w0.254: v1(44.196,21.844) 44.264,21.844 44.518,21.59 59.309,21.59 P2.2
USART3_RX: R20.1 U11.24 | length 4.3
  Top Layer w0.254: U11.24 47.962,12.363 48.514,11.811 49.784,11.811 50.165,11.43 R20.1
USART3_TX: R19.1 U11.39 | length 19.9
  Top Layer w0.254: v1(46.574,22.144) 46.574,22.05 46.962,21.662 U11.39 ; v1(48.014,22.144) 50.881,22.144 53.34,19.685 53.34,12.446 52.832,11.938 52.324,11.938 51.689,11.303 R19.1
  Bottom Layer w0.254: v1(46.574,22.144) v1(48.014,22.144)
V3P3: C9.1 U1.15 U1.16 U1.17 | length 6.6
  Top Layer w0.254: U1.15 43.688,26.728 43.688,25.527 C9.1@44.407,24.808 ; U1.16 C9.1@44.407,24.808 ; U1.17 45.057,25.372 C9.1 C9.1@44.407,24.808
V3P32: C10.1 U2.15 U2.16 U2.17 | length 6.3
  Top Layer w0.254: U2.15 16.383,26.56 16.383,25.409 ; C10.1 16.383,25.409 ; U2.16 17.019,25.274 ; U2.17 17.669,25.289 17.654,25.274 17.019,25.274 ; 16.383,25.409 16.518,25.274 17.019,25.274
VDDA: C11.1 C12.1 C15.1 C16.1 C28.1 C29.1 C36.2 C37.2 U3.5 U3.7 U4.5 U4.7 U5.5 U5.7 U6.5 U6.7 U10.5 U11.20 U11.21 | length 212.5
  Top Layer w0.254: v1(10.287,40.513) C11.1 10.373,39.71 U6.5 13.376,39.71 13.716,39.37 13.716,38.735 13.391,38.41 U6.7 ; U4.7 27.503,36.632 27.178,36.957 26.543,36.957 26.203,36.617 U4.5 26.203,35.133 26.208,35.133 26.797,34.544 C16.1 26.035,34.036 25.781,34.29 25.781,36.957 28.287,39.463 28.707,39.463 v1(28.725,39.481) 29.591,40.347 29.591,45.72 30.353,46.482 v1(30.353,47.879) ; v1(35.888,39.631) 35.895,39.624 C15.1 ; C15.1@37.846,39.497 38.059,39.71 U5.5 40.701,39.71 40.701,38.41 U5.7 ; U11.20 45.962,12.585 46.228,12.319 ; C37.2 C36.2 46.228,12.319 ; U11.21 46.462,12.553 46.228,12.319 ; U3.7 54.737,37.084 54.356,37.465 53.721,37.465 53.437,37.181 U3.5 53.437,34.701 C12.1 53.721,33.528 54.102,33.147 56.261,33.147 57.404,34.29 v1(57.404,43.307)
  Top Layer w0.5: U10.5 21.59,13.629 23.495,13.629 23.982,14.116 24.53,14.116 26.035,15.621 29.044,15.621 29.337,15.328 29.337,14.478 35.56,8.255 v2@45.974,8.255 ; v2@46.228,8.509 C37.2 ; v1(57.404,43.307) 60.325,43.307 64.008,39.624 64.008,8.002 v2(63.007,7.001)
  Bottom Layer w0.254: v1(10.287,40.513) 10.287,44.45 13.716,47.879 v1(30.353,47.879) 54.61,47.879 57.404,45.085 v1(57.404,43.307) ; v1(28.725,39.481) 28.868,39.624 35.881,39.624 v1(35.888,39.631)
  Bottom Layer w0.5: v2(45.989,8.271) 53.451,8.271 54.737,6.985 v2@62.992,6.985
VDDP: C20.1 C21.2 D12.1 D13.2 U7.3 U8.3
pads on no net: U1.12 U1.13 U1.18 U1.19 U1.21 U2.12 U2.13 U2.18 U2.19 U2.21 U7.5 U8.1 U9.4 U10.4 U11.3 U11.4 U11.12 U11.15 U11.17 U11.18 U11.19 U11.25 U11.26 U11.27 U11.28 U11.29 U11.34 U11.40 U11.42 U11.43

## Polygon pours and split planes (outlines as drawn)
AGND on Bottom Layer "AGND_L02_P030" (solid, remove dead copper, pour order 30): 0,0 0,50 65,50 65,0
M_PWR on Bottom Layer "NONET_L-01_P-001" (solid, pour order 28): 29.718,18.923 24.511,24.13 15.875,24.13 14.224,25.781 8.763,25.781 8.763,28.956 10.422,30.615 13.724,30.615 13.97,30.861 13.97,34.29 10.16,34.29 5.461,29.591 5.461,24.638 8.128,21.971 20.828,21.971 23.495,19.304 24.384,19.304 24.384,17.272 25.908,15.748 29.845,15.748
PGND on Bottom Layer "NONET_L-01_P-001" (solid, remove dead copper, pour order 26): 10.795,18.669 15.494,13.97 15.494,7.874 11.557,3.937 11.557,0.381 0.127,0.381 0,0.508 0.127,0.635 0.127,18.669
Net12V_0 on Bottom Layer "NONET_L-01_P-001" (solid, pour order 0): 22.86,12.573 22.86,10.16 19.558,6.858 14.097,6.858 12.7,5.461 12.7,4.572 12.827,4.572 13.208,4.191 25.146,4.191 27.686,6.731 27.686,12.573
M2_CS3 on Bottom Layer "NONET_L-01_P-001" (solid, pour order 21): 22.86,45.085 22.86,37.846 20.32,35.306 18.669,35.306 18.034,35.941 18.161,36.068 18.161,39.243 20.574,41.656 20.574,45.085
PGND on Bottom Layer "NONET_L-01_P-001" (solid, pour order 24): 9.144,29.083 10.795,30.734 13.589,30.734 15.367,32.512 15.621,32.258 50.165,32.258 51.308,31.115 51.308,28.321 41.91,28.321 39.497,25.908 39.37,26.035 37.211,26.035 37.211,26.67 33.909,29.972 25.146,29.972 20.955,25.781 9.144,25.781
M1_CS3 on Bottom Layer "NONET_L-01_P-001" (solid, pour order 11): 47.371,45.085 47.371,38.608 45.593,36.83 45.72,36.703 45.72,34.036 46.101,33.655 46.99,33.655 49.53,36.195 49.53,45.085
M_PWR on Bottom Layer "NONET_L-01_P-001" (solid, pour order 22): 23.114,35.179 39.37,35.179 39.37,34.163 37.719,32.512 36.957,33.274 22.479,33.274
M_PWR on Bottom Layer "NONET_L-01_P-001" (solid, pour order 19): 11.43,34.417 15.494,34.417 16.256,35.179 24.765,35.179 25.019,34.925 25.019,34.036 24.257,34.036 22.733,32.512 15.367,32.512 13.716,30.861 11.176,30.861
M_PWR on Bottom Layer "NONET_L-01_P-001" (solid, pour order 12): 37.338,34.163 38.735,35.56 51.181,35.56 52.705,34.036 52.705,32.131 52.578,32.131 51.562,31.115 40.894,31.115 40.259,30.48 37.719,30.48 37.338,30.861
AGND on Top Layer "AGND_L01_P029" (solid, remove dead copper, pour order 29): 0.019,0.001 0.019,50.001 65.019,50.001 65.019,0.001
PGND on Top Layer "NONET_L-01_P-001" (solid, pour order 27): 9.398,29.083 9.144,29.083 3.556,23.495 0,23.495 0,5.207 4.699,5.207 5.588,4.318 11.938,4.318 15.494,7.874 15.494,13.716 15.113,14.097 12.192,14.097 10.922,15.367 10.922,22.225 12.827,24.13
PGND on Top Layer "NONET_L-01_P-001" (solid, pour order 23): 15.113,35.052 15.113,30.607 13.589,29.083 9.398,29.083 9.398,26.924 12.446,23.876 18.415,23.876 20.193,25.654 25.273,25.654 25.273,29.591 21.792,33.072 17.347,33.072 16.637,33.782 16.637,35.052
M2_CS1 on Top Layer "NONET_L-01_P-001" (solid, pour order 18): 22.86,38.227 21.463,36.83 21.463,31.877 22.098,31.242 22.479,31.242 22.479,31.369 22.606,31.496 22.606,34.163 24.638,36.195 24.638,36.957
M2_CS2 on Top Layer "NONET_L-01_P-001" (solid, pour order 16): 20.32,38.227 20.193,36.576 19.939,35.179 19.939,31.496 20.066,31.369 20.447,31.369 20.574,31.496 20.574,32.893 21.463,34.544 22.098,36.703 21.717,38.227
OUT3 on Top Layer "NONET_L-01_P-001" (solid, pour order 15): 25.273,45.085 25.273,43.307 24.765,42.799 24.13,42.799 22.479,41.148 22.479,39.751 22.86,39.37 23.116,39.626 24.386,39.626 24.386,40.769 24.638,41.021 25.019,41.021 26.035,42.037 26.035,42.545 26.289,42.545 27.432,43.688 27.432,45.085
PGND on Top Layer "NONET_L-01_P-001" (solid, pour order 13): 43.307,35.179 43.307,32.131 40.767,29.591 37.719,29.591 37.592,29.464 37.592,25.654 40.386,25.654 42.545,27.813 45.085,27.813 45.339,27.559 45.339,24.765 51.435,24.765 53.34,26.67 53.34,27.813 52.832,27.813 50.257,30.388 50.257,33.097 45.643,33.097 44.45,34.29 44.45,35.179
M1_CS2 on Top Layer "NONET_L-01_P-001" (solid, pour order 9): 49.276,37.973 49.276,36.322 48.006,35.052 48.006,31.877 47.752,31.623 47.371,31.623 47.371,33.274 47.244,33.401 47.244,36.322 47.498,36.576
M1_CS1 on Top Layer "NONET_L-01_P-001" (solid, pour order 8): 51.816,36.957 51.816,36.195 49.911,34.29 49.911,32.004 49.657,31.75 49.53,31.877 49.403,31.877 49.403,33.147 49.276,33.274 49.276,37.211 50.038,37.973
OUT1 on Top Layer "NONET_L-01_P-001" (solid, pour order 7): 52.07,44.958 54.737,44.958 54.737,42.926 53.467,42.926 52.832,42.291 52.832,41.656 51.562,40.386 49.657,40.386 49.784,40.513 49.784,41.402 52.07,43.688
VDDP on Top Layer "NONET_L-01_P-001" (solid, pour order 1): 26.797,15.113 26.797,12.446 27.051,12.192 27.051,10.16 26.035,9.144 18.669,9.144 17.272,10.541 12.573,10.541 9.144,13.97 9.144,16.383 7.62,16.383 7.493,16.256 7.493,14.605 7.747,14.351 7.747,10.668 8.509,9.906 11.303,9.906 12.573,8.636 12.573,7.62 13.843,6.35 30.861,6.35 32.258,7.747 32.258,12.7 29.845,15.113
5V on Top Layer "NONET_L-01_P-001" (solid, pour order 5): 13.462,17.018 14.351,17.018 14.859,16.51 14.859,15.875 15.113,15.621 18.796,15.621 18.796,16.891 19.939,16.891 19.939,15.621 19.812,15.621 19.939,15.494 20.701,15.494 20.701,18.415 20.066,19.05 19.304,19.05 19.304,17.907 19.05,17.653 18.161,17.653 18.034,17.78 18.034,19.05 17.526,19.05 16.764,18.288 13.843,18.288
5V on Top Layer "NONET_L-01_P-001" (solid, pour order 4): 9.398,24.13 11.176,24.13 14.224,21.082 14.224,17.399 13.843,17.018 13.081,17.018 12.7,16.637 12.7,15.748 11.811,15.748 11.684,15.875 11.684,17.526 12.7,17.526 12.7,19.558 10.922,21.336 9.525,21.336 9.398,21.463
M2_CS3 on Top Layer "NONET_L-01_P-001" (solid, pour order 20): 19.939,31.496 20.413,31.97 20.413,37.931 18.465,37.931 18.161,37.627 18.161,35.814 19.304,34.671 19.304,31.369
OUT4 on Top Layer "NONET_L-01_P-001" (solid, pour order 14): 22.86,45.085 22.86,43.942 21.844,42.926 21.082,42.926 20.32,42.164 20.32,40.767 21.336,40.767 22.098,40.005 22.479,40.386 22.479,41.148 24.13,42.799 24.765,42.799 25.273,43.307 25.273,45.085
M1_CS3 on Top Layer "NONET_L-01_P-001" (solid, pour order 10): 47.371,31.623 47.244,31.75 47.244,35.941 46.736,36.449 46.101,36.449 46.101,33.909 46.736,33.274 46.736,31.623
OUT2 on Top Layer "NONET_L-01_P-001" (solid, pour order 6): 49.784,44.958 49.784,43.688 48.006,41.91 47.752,41.91 47.498,41.656 47.498,40.513 48.387,40.513 49.276,39.624 49.403,39.751 49.403,40.894 52.07,43.561 52.07,44.958
NetC19_2 on Top Layer "NONET_L-01_P-001" (solid, pour order 2): 7.493,14.605 7.493,17.272 4.445,17.272 3.937,17.78 3.937,20.32 4.445,20.828 4.191,21.082 4.191,21.971 2.54,21.971 2.159,21.59 2.159,17.78 3.683,16.256 6.35,16.256 6.35,14.605

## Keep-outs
Keep-Out Layer:
  circle w0.1: c3,3 r2
  circle w0.1: c62,47 r1.25
  circle w0.1: c62,47 r2
  circle w0.1: c62,3 r1.25
  circle w0.1: c62,3 r2
  circle w0.1: c3,3 r1.25
  circle w0.1: c3,47 r1.25
  circle w0.1: c3,47 r2
  lines w0.1: 0,0 65,0 65,50 0,50 0,0

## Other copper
Top Layer:
  rectangle net M_PWR: 24.638,16.129 27.813,20.32
  rectangle net M_PWR: 22.733,33.401 23.495,34.163
  rectangle net M_PWR: 22.606,31.496 23.114,34.163
  rectangle net M_PWR: 17.018,33.401 18.542,35.306
  rectangle net M_PWR: 18.034,31.496 18.542,34.544
  rectangle net M_PWR: 11.684,30.861 13.589,34.417
  rectangle net M_PWR: 44.577,33.401 45.847,35.56
  rectangle net M_PWR: 38.481,30.861 40.513,34.925
  rectangle net NetC19_1: 4.445,17.907 5.969,18.415
Bottom Layer:
  rectangle net 5V: 12.192,19.685 13.97,21.209

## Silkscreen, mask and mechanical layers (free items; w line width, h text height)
Top Overlay:
  lines w0.254: 0,44 19,44 ; 46,44 65,44
  text "FOC DRIVER V0.4" at 3.789,27.94 h2 r90
  text "2024.8 TIANXIAOHUA" at 5.699,27.939 h1.52 r90
  text "RXD" at 56.007,21.082 h2
  text "TXD" at 56.108,18.504 h2
  text "VCC" at 55.849,15.885 h2
  text "GND" at 55.764,13.266 h2
  text "DIO" at 56.585,10.645 h2
  text "CLK" at 56.161,8.023 h2
  text "ON" at 32.287,4.699 h2.5 r270
  text "TX RX GND" at 48.387,4.215 h2
  text "OFF" at 18.259,0.889 h2.5 r90
Bottom Overlay:
  text "SCL" at 46.715,42.545 h2 r90
  text "OUTB" at 51.922,42.545 h2 r90
  text "OUTC" at 54.462,42.545 h2 r90
  text "SCL" at 19.41,42.418 h2 r90
  text "OUTB" at 24.617,42.418 h2 r90
  text "OUTC" at 27.157,42.418 h2 r90
  text "GND" at 39.222,42.418 h2 r90
  text "5V" at 41.762,42.418 h2 r90
  text "SDA" at 44.302,42.418 h2 r90
  text "GND" at 11.917,42.291 h2 r90
  text "5V" at 14.457,42.291 h2 r90
  text "SDA" at 16.997,42.291 h2 r90
  text "OUTA" at 49.382,42.291 h2 r90
  text "OUTA" at 22.077,42.164 h2 r90
  text "RXD" at 59.76,21.209 h2
  text "TXD" at 59.76,18.632 h2
  text "VCC" at 59.76,16.012 h2
  text "GND" at 59.76,13.391 h2
  text "8~12V" at 14.203,11.811 h2 r90
  text "GND" at 11.536,10.922 h2 r90
  text "DIO" at 59.76,10.77 h2
  text "CLK" at 59.76,8.15 h2
Top Solder:
  circle w1: c3,3 r1.5
  circle w1: c62,47 r1.5
  circle w1: c62,3 r1.5
  circle w1: c3,47 r1.5
Bottom Solder:
  circle w1: c3,3 r1.5
  circle w1: c62,47 r1.5
  circle w1: c62,3 r1.5
  circle w1: c3,47 r1.5

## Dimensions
3,4.5 to 0,0 on Mechanical 1
0,50 to 65,50 on Mechanical 1
0,0 to 0,50 on Mechanical 1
